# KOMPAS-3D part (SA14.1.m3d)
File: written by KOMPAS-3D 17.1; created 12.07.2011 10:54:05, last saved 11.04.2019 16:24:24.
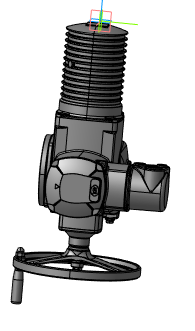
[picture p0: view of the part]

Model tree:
1. Плоскость XY
2. Плоскость ZX
3. Плоскость ZY
4. Ось X
5. Ось Y
6. Ось Z
7. Начало координат
8. Операция без истории:2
